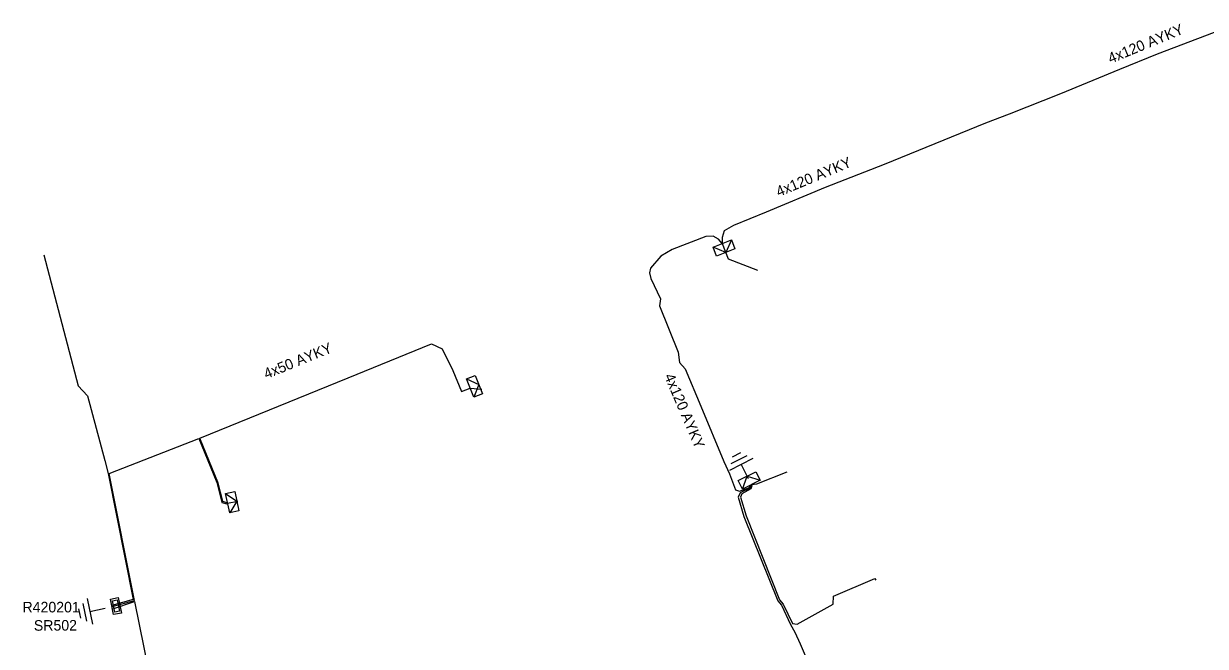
# Model space of a CAD drawing. Extents: x -540028 to -538776, y -1157064 to -1155670.
# Drawn here: x -539722.6 to -539610.5, y -1155813.9 to -1155754.8 of the extents above; entities that cross this region are included whole.
import ezdxf

# ---------------------------------------------------------------- set-up
doc = ezdxf.new("R2010")
doc.units = 0
for name, color, linetype in [('Vrstva 15', 7, 'Continuous'), ('Vrstva 2', 7, 'Continuous'), ('Vrstva 28', 7, 'Continuous'), ('Vrstva 29', 7, 'Continuous'), ('Vrstva 30', 7, 'Continuous'), ('Vrstva 31', 7, 'Continuous'), ('Vrstva 5', 7, 'Continuous'), ('Vrstva 52', 7, 'Continuous'), ('Vrstva 59', 7, 'Continuous'), ('Vrstva 6', 7, 'Continuous')]:
    doc.layers.add(name, color=color, linetype=linetype)

# ---------------------------------------------------------------- blocks, each defined once
blk = doc.blocks.new('132')
at = {"layer": 'Vrstva 2'}
for points in [[(-1.5, 1.5), (1.5, 1.5), (1.5, 0), (-1.5, 0)], [(-1.1, 1.2), (1.1, 1.2), (1.1, 0.3), (-1.1, 0.3)]]:
    blk.add_lwpolyline(points, close=True, dxfattribs=at)
blk = doc.blocks.new('23')
at = {"layer": 'Vrstva 2'}
blk.add_lwpolyline([(1.875, -1.8), (-1.875, -1.8), (-1.875, 0), (1.875, 0)], close=True, dxfattribs=at)
blk.add_lwpolyline([(1.875, 0), (0, -1.8), (-1.875, 0)], dxfattribs=at)
blk = doc.blocks.new('11')
at = {"layer": 'Vrstva 2'}
for p, q in [((0, -4.3), (0, -1.3)), ((-2.5, -4.3), (2.5, -4.3)), ((-1.7, -5.3), (1.7, -5.3)), ((-0.9, -6.3), (0.9, -6.3))]:
    blk.add_line(p, q, dxfattribs=at)

msp = doc.modelspace()

# ---------------------------------------------------------------- linework, layer by layer
at = {"layer": 'Vrstva 5'}
for points in [[(-539609.69, -1155755.65), (-539615.1, -1155757.69), (-539618.67, -1155759.16), (-539624.26, -1155761.45), (-539629.13, -1155763.38), (-539631.38, -1155764.24), (-539640.97, -1155768.17), (-539646.59, -1155770.36), (-539652.16, -1155772.69), (-539655.27, -1155773.94), (-539656.15, -1155774.45), (-539656.35, -1155775.09), (-539656.33, -1155775.66), (-539656.69, -1155775.23), (-539657.18, -1155774.95), (-539657.9, -1155774.99), (-539661.08, -1155776.22), (-539662.16, -1155776.84), (-539663.14, -1155777.99), (-539663.23, -1155778.45), (-539663.11, -1155778.98), (-539662.2, -1155780.91), (-539662.29, -1155781.56), (-539660.52, -1155785.95), (-539660.39, -1155786.94), (-539659.86, -1155787.54), (-539658.35, -1155791.07), (-539656.19, -1155796.31), (-539655.64, -1155797.5), (-539655.09, -1155799), (-539654.71, -1155799.15), (-539653.75, -1155798.78), (-539653.7, -1155798.63), (-539653.57, -1155798.52), (-539653.6, -1155798.6), (-539653.71, -1155798.86), (-539654.64, -1155799.3), (-539654.82, -1155799.7), (-539654.28, -1155801.53), (-539651.07, -1155809.53), (-539650.71, -1155809.96), (-539649.85, -1155811.77), (-539649.45, -1155812.5), (-539648.95, -1155813.6), (-539647.94, -1155815.98)], [(-539720.64, -1155776.73), (-539717.39, -1155789.15), (-539716.5, -1155790.09), (-539714.86, -1155796.22), (-539714.54, -1155797.47), (-539712.17, -1155809.42), (-539714.19, -1155809.98)], [(-539714.17, -1155810.08), (-539712.05, -1155809.5), (-539714.44, -1155797.45), (-539705.95, -1155794.15), (-539704.24, -1155798.32), (-539703.76, -1155800.2), (-539703.31, -1155800.34), (-539703.22, -1155800.28), (-539703.31, -1155800.24), (-539703.68, -1155800.12), (-539704.14, -1155798.28), (-539705.85, -1155794.11), (-539691.81, -1155788.38), (-539683.9, -1155785.18), (-539682.88, -1155785.63), (-539681.87, -1155787.71), (-539681.06, -1155789.7), (-539680.24, -1155789.37)], [(-539714.12, -1155810.3), (-539712.05, -1155809.6), (-539708.5, -1155827.03), (-539707.21, -1155826.69), (-539707.35, -1155826.13), (-539707.43, -1155826.04)]]:
    msp.add_lwpolyline(points, dxfattribs=at)
at = {"layer": 'Vrstva 52'}
for points in [[(-539656.33, -1155775.66), (-539655.76, -1155777.1), (-539652.98, -1155778.19)], [(-539653.57, -1155798.52), (-539653.06, -1155798.44), (-539650.18, -1155797.3)], [(-539653.57, -1155798.52), (-539653.52, -1155798.64), (-539653.63, -1155798.93), (-539654.49, -1155799.4), (-539654.6, -1155799.71), (-539654.08, -1155801.47), (-539650.89, -1155809.43), (-539650.55, -1155809.86), (-539649.67, -1155811.69), (-539649.23, -1155811.76), (-539645.82, -1155809.86), (-539645.79, -1155809.08), (-539641.88, -1155807.42), (-539641.76, -1155807.59)]]:
    msp.add_lwpolyline(points, dxfattribs=at)
at = {"layer": 'Vrstva 59'}
for points in [[(-539680.24, -1155789.37), (-539679.12, -1155789.46)], [(-539703.22, -1155800.29), (-539702.24, -1155800.08)]]:
    msp.add_lwpolyline(points, dxfattribs=at)

# ---------------------------------------------------------------- block references
at = {"layer": 'Vrstva 15', "yscale": 0.5}
for p, xscale, rotation in [((-539653.57, -1155798.52), 0.5, -153.15182495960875), ((-539714.18, -1155810.11), 0.5000000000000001, -78.61149162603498)]:
    msp.add_blockref('11', p, dxfattribs=dict(at, xscale=xscale, rotation=rotation))
at = {"layer": 'Vrstva 28', "xscale": 0.49999999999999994, "yscale": 0.5000000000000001, "rotation": -78.40672498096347}
msp.add_blockref('132', (-539714.18, -1155810.11), dxfattribs=at)
at = {"layer": 'Vrstva 31', "xscale": 0.5}
for p, yscale, rotation in [((-539656.33, -1155775.66), 0.5, 21.58204997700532), ((-539680.24, -1155789.37), 0.49999999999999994, 112.0543610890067), ((-539653.57, -1155798.52), 0.5, -153.15182492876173), ((-539703.22, -1155800.28), 0.5000000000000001, 101.79568891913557)]:
    msp.add_blockref('23', p, dxfattribs=dict(at, yscale=yscale, rotation=rotation))

# ---------------------------------------------------------------- texts
at = {"layer": 'Vrstva 29'}
msp.add_text('R420201', height=1, dxfattribs=at).set_placement((-539722.67, -1155810.63))
at = {"layer": 'Vrstva 30'}
msp.add_text('SR502', height=1, rotation=0.295, dxfattribs=at).set_placement((-539721.59, -1155812.37))
at = {"layer": 'Vrstva 6'}
for s, rotation, p in [('4x120 AYKY', 22.38, (-539619.52, -1155758.61)), ('4x120 AYKY', 22.7, (-539650.98, -1155771.25)), ('4x50 AYKY', 22.199, (-539699.55, -1155788.52)), ('4x120 AYKY', 293.159, (-539661.85, -1155788.23))]:
    msp.add_text(s, height=1, rotation=rotation, dxfattribs=at).set_placement(p)

doc.saveas('drawing.dxf')
